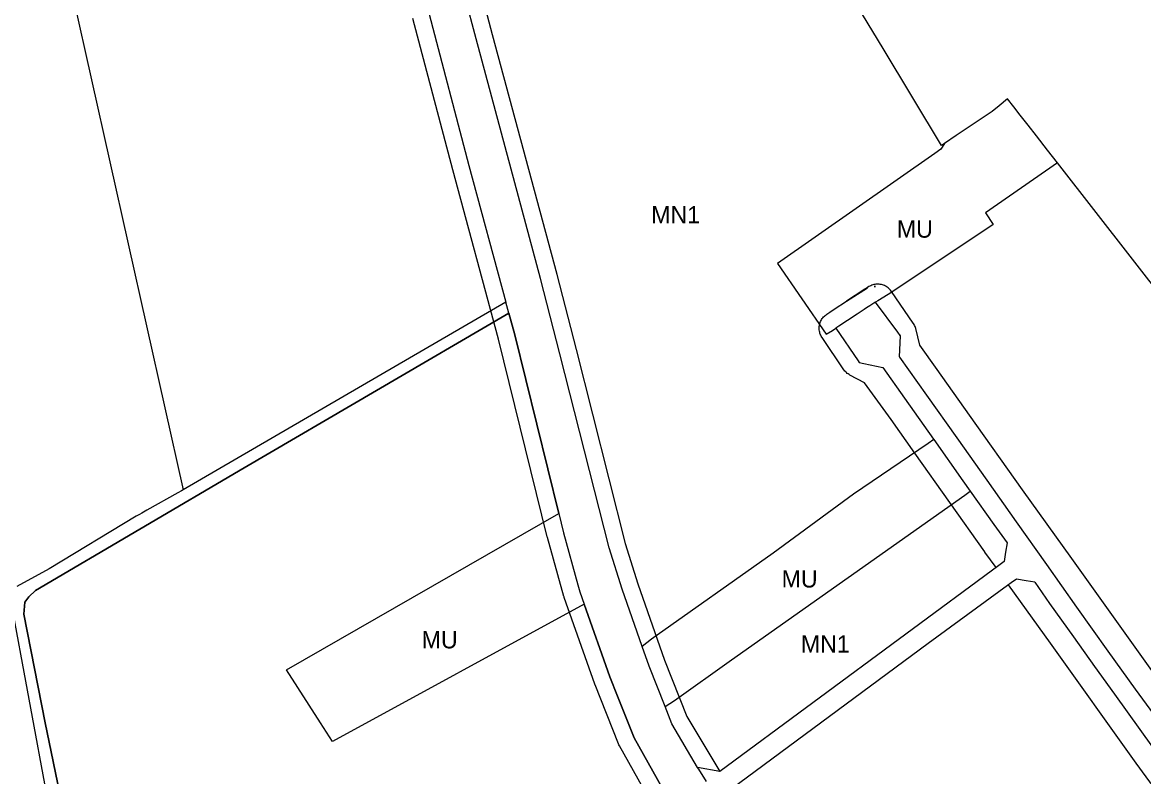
# Model space of a CAD drawing. Extents: x 7435758 to 7439981, y 5550649 to 5554049.
# Drawn here: x 7437108.2 to 7437444.8, y 5552138.3 to 5552364.7 of the extents above; entities that cross this region are included whole.
import ezdxf

# ---------------------------------------------------------------- set-up
doc = ezdxf.new("R2010")
doc.units = 0
for name, color, linetype in [('_Tereny_wyrok', 7, 'Continuous'), ('linie_rozgraniczające', 7, 'Continuous'), ('linie_zabudowy_nieprzekraczalne', 7, 'Continuous'), ('oznaczenia_przeznaczen', 7, 'Continuous')]:
    doc.layers.add(name, color=color, linetype=linetype)

msp = doc.modelspace()

# ---------------------------------------------------------------- linework, layer by layer
at = {"layer": '_Tereny_wyrok'}
for p, q in [((7437254.27, 5552277.38), (7437174.82, 5552230.93)), ((7437256.04, 5552270.85), (7437254.27, 5552277.38)), ((7437269.23, 5552217.2), (7437256.04, 5552270.85)), ((7437174.82, 5552230.93), (7437112.18, 5552194.08)), ((7437187.49, 5552170.33), (7437269.23, 5552217.2)), ((7437110.17, 5552192.24), (7437108.96, 5552190.6)), ((7437112.18, 5552194.08), (7437110.17, 5552192.24)), ((7437108.96, 5552190.6), (7437108.62, 5552187.06)), ((7437276.92, 5552189.99), (7437201.36, 5552148.79)), ((7437284.61, 5552168.24), (7437276.92, 5552189.99)), ((7437108.62, 5552187.06), (7437115.07, 5552154.38)), ((7437197.73, 5552154.43), (7437187.49, 5552170.33)), ((7437284.8, 5552167.7), (7437284.61, 5552168.24)), ((7437286.68, 5552162.96), (7437284.8, 5552167.7)), ((7437291.87, 5552149.93), (7437286.68, 5552162.96)), ((7437115.07, 5552154.38), (7437136.22, 5552051.57)), ((7437201.36, 5552148.79), (7437197.73, 5552154.43)), ((7437301.69, 5552132.42), (7437291.87, 5552149.93))]:
    msp.add_line(p, q, dxfattribs=at)
at = {"layer": 'linie_rozgraniczające'}
for p, q in [((7437079.69, 5552568.34), (7437156.51, 5552224.35)), ((7437366.62, 5552356.85), (7437322.07, 5552430.86)), ((7437244.46, 5552359.72), (7437240.84, 5552373.46)), ((7437230.33, 5552367.12), (7437242.26, 5552321.71)), ((7437254.97, 5552320.65), (7437244.46, 5552359.72)), ((7437384.15, 5552327.72), (7437366.62, 5552356.85)), ((7437404.02, 5552341.71), (7437401.44, 5552339.58)), ((7437405.85, 5552339.36), (7437404.02, 5552341.71)), ((7437399.4, 5552337.9), (7437396.39, 5552335.89)), ((7437401.44, 5552339.58), (7437399.4, 5552337.9)), ((7437407.81, 5552336.84), (7437405.85, 5552339.36)), ((7437410.14, 5552333.85), (7437407.81, 5552336.84)), ((7437396.39, 5552335.89), (7437388.59, 5552330.68)), ((7437412.64, 5552330.63), (7437410.14, 5552333.85)), ((7437388.59, 5552330.68), (7437385.04, 5552328.32)), ((7437415.98, 5552326.35), (7437412.64, 5552330.63)), ((7437384, 5552326.57), (7437382.18, 5552325.29)), ((7437385.04, 5552328.32), (7437384, 5552326.57)), ((7437385.04, 5552328.32), (7437384.15, 5552327.72)), ((7437382.18, 5552325.29), (7437334.96, 5552292.27)), ((7437418.98, 5552322.48), (7437415.98, 5552326.35)), ((7437242.26, 5552321.71), (7437253.38, 5552280.67)), ((7437263.81, 5552287.76), (7437254.97, 5552320.65)), ((7437418.98, 5552322.48), (7437397.35, 5552307.52)), ((7437516.1, 5552197.62), (7437418.98, 5552322.48)), ((7437397.35, 5552307.52), (7437399.69, 5552303.96)), ((7437399.69, 5552303.96), (7437369.51, 5552283.88)), ((7437334.96, 5552292.27), (7437349.56, 5552271.08)), ((7437269.61, 5552265.22), (7437263.81, 5552287.76)), ((7437369.44, 5552283.81), (7437365.01, 5552281.08)), ((7437369.51, 5552283.88), (7437369.44, 5552283.81)), ((7437253.34, 5552280.68), (7437220.13, 5552261.4)), ((7437253.38, 5552280.67), (7437253.34, 5552280.68)), ((7437254.27, 5552277.38), (7437253.38, 5552280.67)), ((7437362.29, 5552279.34), (7437360.99, 5552278.49)), ((7437362.39, 5552279.41), (7437362.29, 5552279.34)), ((7437363.85, 5552280.37), (7437362.39, 5552279.41)), ((7437364.34, 5552280.67), (7437363.85, 5552280.37)), ((7437363.85, 5552280.37), (7437363.85, 5552280.37)), ((7437365.01, 5552281.08), (7437364.34, 5552280.67)), ((7437371.06, 5552271.67), (7437364.34, 5552280.67)), ((7437174.82, 5552230.93), (7437254.27, 5552277.38)), ((7437254.27, 5552277.38), (7437256.04, 5552270.85)), ((7437358.84, 5552277.08), (7437355.98, 5552275.2)), ((7437360.99, 5552278.49), (7437358.84, 5552277.08)), ((7437351.43, 5552272.2), (7437352.43, 5552272.86)), ((7437352.45, 5552272.88), (7437352.43, 5552272.86)), ((7437352.43, 5552272.86), (7437359.11, 5552263.09)), ((7437353.35, 5552273.47), (7437352.45, 5552272.88)), ((7437355.98, 5552275.2), (7437353.35, 5552273.47)), ((7437256.04, 5552270.85), (7437269.23, 5552217.2)), ((7437349.56, 5552271.08), (7437351.43, 5552272.2)), ((7437371.79, 5552270.7), (7437371.06, 5552271.67)), ((7437371.52, 5552264.31), (7437371.81, 5552270.6)), ((7437371.82, 5552270.67), (7437371.79, 5552270.7)), ((7437371.81, 5552270.6), (7437371.82, 5552270.67)), ((7437284.35, 5552206.9), (7437269.61, 5552265.22)), ((7437359.11, 5552263.09), (7437359.48, 5552262.54)), ((7437359.48, 5552262.54), (7437360.8, 5552262.26)), ((7437371.66, 5552264.12), (7437371.52, 5552264.31)), ((7437379.76, 5552252.77), (7437371.66, 5552264.12)), ((7437220.13, 5552261.4), (7437156.51, 5552224.35)), ((7437360.8, 5552262.26), (7437366.56, 5552261.03)), ((7437366.56, 5552261.03), (7437373.02, 5552251.83)), ((7437388.85, 5552239.92), (7437379.76, 5552252.77)), ((7437373.02, 5552251.83), (7437381.76, 5552239.54)), ((7437381.85, 5552239.42), (7437380.21, 5552238.29)), ((7437381.76, 5552239.54), (7437381.85, 5552239.42)), ((7437381.85, 5552239.42), (7437390.59, 5552227.08)), ((7437397.86, 5552227.21), (7437388.85, 5552239.92)), ((7437380.2, 5552238.3), (7437357.78, 5552223.09)), ((7437380.21, 5552238.29), (7437380.2, 5552238.3)), ((7437112.18, 5552194.08), (7437174.82, 5552230.93)), ((7437390.59, 5552227.08), (7437392.81, 5552223.94)), ((7437406.64, 5552214.78), (7437397.86, 5552227.21)), ((7437154.93, 5552223.46), (7437145.61, 5552218.23)), ((7437156.01, 5552224.06), (7437154.93, 5552223.46)), ((7437156.51, 5552224.35), (7437156.01, 5552224.06)), ((7437321.15, 5552173.29), (7437391.19, 5552222.77)), ((7437357.78, 5552223.09), (7437333.62, 5552205.36)), ((7437391.18, 5552222.78), (7437392.81, 5552223.94)), ((7437391.19, 5552222.77), (7437391.18, 5552222.78)), ((7437392.81, 5552223.94), (7437399.86, 5552213.99)), ((7437142.42, 5552216.41), (7437116.22, 5552200.66)), ((7437143.39, 5552216.99), (7437142.42, 5552216.41)), ((7437144.04, 5552217.35), (7437143.39, 5552216.99)), ((7437145.61, 5552218.23), (7437144.04, 5552217.35)), ((7437187.49, 5552170.33), (7437269.23, 5552217.2)), ((7437269.23, 5552217.2), (7437270.66, 5552211.39)), ((7437399.86, 5552213.99), (7437403.84, 5552208.39)), ((7437415.77, 5552201.94), (7437406.64, 5552214.78)), ((7437270.66, 5552211.39), (7437275.01, 5552195.81)), ((7437288.27, 5552194.53), (7437284.35, 5552206.9)), ((7437333.62, 5552205.36), (7437297.06, 5552179.5)), ((7437403.39, 5552205.59), (7437402.94, 5552202.79)), ((7437403.84, 5552208.39), (7437403.39, 5552205.59)), ((7437402.94, 5552202.79), (7437401.33, 5552201.61)), ((7437424.78, 5552189.16), (7437415.77, 5552201.94)), ((7437116.22, 5552200.66), (7437106.53, 5552195.37)), ((7437401.33, 5552201.61), (7437317.61, 5552139.76)), ((7437275.01, 5552195.81), (7437275.61, 5552193.69)), ((7437403.96, 5552195.62), (7437380.16, 5552178.26)), ((7437405.11, 5552196.45), (7437403.96, 5552195.62)), ((7437406.64, 5552197.56), (7437405.11, 5552196.45)), ((7437409.57, 5552197.05), (7437406.64, 5552197.56)), ((7437412.16, 5552196.6), (7437409.57, 5552197.05)), ((7437412.16, 5552196.6), (7437416.63, 5552190.24)), ((7437104.48, 5552192.3), (7437129.36, 5552057.48)), ((7437108.96, 5552190.6), (7437110.17, 5552192.24)), ((7437110.17, 5552192.24), (7437112.18, 5552194.08)), ((7437275.61, 5552193.69), (7437276.92, 5552189.99)), ((7437294.3, 5552177.32), (7437288.27, 5552194.53)), ((7437108.62, 5552187.06), (7437108.96, 5552190.6)), ((7437276.92, 5552189.99), (7437201.36, 5552148.79)), ((7437276.92, 5552189.99), (7437284.61, 5552168.24)), ((7437416.63, 5552190.24), (7437423.78, 5552180.21)), ((7437434.2, 5552175.93), (7437424.78, 5552189.16)), ((7437115.07, 5552154.38), (7437108.62, 5552187.06)), ((7437297.06, 5552179.5), (7437294.3, 5552177.32)), ((7437423.78, 5552180.21), (7437430.1, 5552171.36)), ((7437296.36, 5552171.43), (7437294.3, 5552177.32)), ((7437380.16, 5552178.26), (7437320.93, 5552134.39)), ((7437442.45, 5552164.48), (7437434.2, 5552175.93)), ((7437303.97, 5552161.15), (7437321.15, 5552173.29)), ((7437197.73, 5552154.43), (7437187.49, 5552170.33)), ((7437284.61, 5552168.24), (7437284.8, 5552167.7)), ((7437301.2, 5552159.28), (7437296.36, 5552171.43)), ((7437430.1, 5552171.36), (7437436.07, 5552163.04)), ((7437284.8, 5552167.7), (7437286.68, 5552162.96)), ((7437286.68, 5552162.96), (7437291.87, 5552149.93)), ((7437436.07, 5552163.04), (7437447.53, 5552147.14)), ((7437448.98, 5552155.5), (7437442.45, 5552164.48)), ((7437301.2, 5552159.28), (7437303.97, 5552161.15)), ((7437303.25, 5552154.13), (7437301.2, 5552159.28)), ((7437136.22, 5552051.57), (7437115.07, 5552154.38)), ((7437201.36, 5552148.79), (7437197.73, 5552154.43)), ((7437310.95, 5552141.04), (7437303.25, 5552154.13)), ((7437291.87, 5552149.93), (7437301.69, 5552132.42)), ((7437311.29, 5552140.46), (7437310.95, 5552141.04)), ((7437317.61, 5552139.76), (7437310.95, 5552141.04)), ((7437313.58, 5552136.79), (7437311.29, 5552140.46))]:
    msp.add_line(p, q, dxfattribs=at)
at = {"layer": 'linie_zabudowy_nieprzekraczalne'}
for points in [[(7437120.71, 5552853.45), (7437125.86, 5552836.94), (7437125.94, 5552836.66), (7437131.09, 5552815.87), (7437153.26, 5552730.42), (7437165.89, 5552683.76), (7437165.92, 5552683.63), (7437165.93, 5552683.61), (7437177.48, 5552635.16), (7437206.88, 5552523.96), (7437206.89, 5552523.93), (7437225.25, 5552452.28), (7437249.29, 5552361.01), (7437268.64, 5552289.06), (7437268.66, 5552289.01), (7437274.45, 5552266.46), (7437274.46, 5552266.44), (7437289.16, 5552208.27), (7437293.01, 5552196.12), (7437301.05, 5552173.18), (7437307.75, 5552156.34), (7437317.61, 5552139.76)], [(7437297.33, 5552129.98), (7437287.5, 5552147.48), (7437287.47, 5552147.53), (7437287.33, 5552147.83), (7437287.22, 5552148.08), (7437280.15, 5552165.86), (7437280.13, 5552165.9), (7437280.08, 5552166.04), (7437270.89, 5552192.03), (7437270.83, 5552192.2), (7437270.79, 5552192.35), (7437265.84, 5552210.05), (7437265.8, 5552210.2), (7437251.2, 5552269.6), (7437237.43, 5552320.41), (7437237.42, 5552320.44), (7437225.49, 5552365.85)], [(7437448.78, 5552168.06), (7437423.25, 5552203.71), (7437408.49, 5552224.35), (7437392.56, 5552246.79), (7437382.85, 5552260.46), (7437377.7, 5552267.73), (7437376.41, 5552272.81), (7437376.34, 5552273.07), (7437376.23, 5552273.38), (7437376.1, 5552273.68), (7437375.96, 5552273.97), (7437375.79, 5552274.25), (7437375.68, 5552274.42), (7437369.13, 5552283.92), (7437369.05, 5552284.03), (7437368.85, 5552284.28), (7437368.63, 5552284.53), (7437368.4, 5552284.76), (7437368.15, 5552284.97), (7437367.89, 5552285.17), (7437367.62, 5552285.35), (7437367.33, 5552285.51), (7437367.04, 5552285.65), (7437366.73, 5552285.78), (7437366.42, 5552285.88), (7437366.11, 5552285.96), (7437365.79, 5552286.02), (7437365.46, 5552286.06), (7437365.13, 5552286.08), (7437364.81, 5552286.08), (7437364.48, 5552286.05), (7437364.16, 5552286.01), (7437363.84, 5552285.94), (7437363.52, 5552285.86), (7437363.21, 5552285.75), (7437362.91, 5552285.62), (7437362.62, 5552285.47), (7437362.39, 5552285.34), (7437361.23, 5552284.63), (7437361.18, 5552284.6), (7437361.11, 5552284.55), (7437355.63, 5552280.95), (7437361.94, 5552284.99)], [(7437363.9, 5552285.37), (7437363.98, 5552285.37), (7437364.3, 5552285.35), (7437364.34, 5552285.35), (7437364.18, 5552285.4), (7437363.9, 5552285.37)], [(7437400.53, 5552201.02), (7437397.18, 5552205.65), (7437397.15, 5552205.69), (7437376.17, 5552235.35), (7437376.13, 5552235.4), (7437369.05, 5552245.41), (7437369.05, 5552245.42), (7437361.08, 5552256.45), (7437356.68, 5552258.79), (7437356.42, 5552258.94), (7437356.15, 5552259.12), (7437355.89, 5552259.31), (7437355.64, 5552259.53), (7437355.41, 5552259.76), (7437355.19, 5552260), (7437354.99, 5552260.26), (7437354.89, 5552260.39), (7437348.31, 5552270.06), (7437348.22, 5552270.2), (7437348.06, 5552270.48), (7437347.91, 5552270.78), (7437347.78, 5552271.08), (7437347.67, 5552271.39), (7437347.59, 5552271.7), (7437347.52, 5552272.02), (7437347.48, 5552272.35), (7437347.45, 5552272.67), (7437347.45, 5552273), (7437347.47, 5552273.33), (7437347.51, 5552273.65), (7437347.57, 5552273.97), (7437347.65, 5552274.29), (7437347.75, 5552274.6), (7437347.88, 5552274.9), (7437348.02, 5552275.2), (7437348.18, 5552275.48), (7437348.36, 5552275.76), (7437348.56, 5552276.02), (7437348.77, 5552276.26), (7437349, 5552276.5), (7437349.25, 5552276.71), (7437349.5, 5552276.92), (7437349.7, 5552277.05), (7437350.6, 5552277.64), (7437351.95, 5552278.53), (7437355.63, 5552280.95)], [(7437605.29, 5551926.09), (7437569.67, 5551972.95), (7437569.66, 5551972.96), (7437549.64, 5551999.44), (7437549.63, 5551999.46), (7437526.05, 5552030.9), (7437526.04, 5552030.9), (7437525.79, 5552031.22), (7437522.21, 5552035.83), (7437513.69, 5552047.43), (7437471.05, 5552103.37), (7437470.99, 5552103.45), (7437442.61, 5552142.29), (7437442.61, 5552142.3), (7437442.58, 5552142.34), (7437416.92, 5552178.36), (7437404.27, 5552195.85)]]:
    msp.add_lwpolyline(points, dxfattribs=at)

# ---------------------------------------------------------------- texts
at = {"layer": 'oznaczenia_przeznaczen'}
for s, p in [('MN1', (7437297.01, 5552304.33)), ('MU', (7437370.74, 5552300.04)), ('MU', (7437336.16, 5552195.03)), ('MU', (7437228.1, 5552176.76)), ('MN1', (7437341.94, 5552175.5))]:
    msp.add_text(s, height=5.2, dxfattribs=at).set_placement(p)

doc.saveas('drawing.dxf')
